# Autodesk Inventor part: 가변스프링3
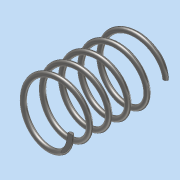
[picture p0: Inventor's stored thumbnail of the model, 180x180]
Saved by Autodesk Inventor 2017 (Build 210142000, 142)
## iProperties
Part Number: 가변스프링3
Material: 강철, 연강
Document SubType Name: Modeling
Designer: MRC
Density: 7.85 g/cm^3
Appearance: 반연마
Mass: 8.42502 g
Surface Area: 21.7259 cm^2
Volume: 1.07325 cm^3
Author: MRC
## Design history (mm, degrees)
sketch "스케치1"
  geometry: L1 (0, 0)-(11, 0); L2 (11, 0)-(11, 37.411); L3 (11, 37.411)-(0, 37.411); L4 (0, 37.411)-(0, 0); C1 r 1 at (11, 0)
  constraints: 8 end point, 2 parallel, 1 centre point, 1 coincident, 1 horizontal, 1 perpendicular
  dimensions: "d0" = 22 diameter of L2 L4; "d1" = 2 diameter of C1; "d2" = 37.4112 distance between parallel lines of L1 L3 (derived)
feature "코일1" sketch "스케치1" pitch "d3" = 10; turns "d5" = 5; dims "d4" = 37.4112 (= d2), "d6" = 0, angle "d7" = 90 deg, angle "d8" = 90 deg, "d9" = 0, "d10" = 0
sketch "스케치2"
  geometry: L1 (-25.076, 37.411)-(25.076, 37.411); L2 (25.076, 37.411)-(25.076, 0); L3 (25.076, 0)-(-25.076, 0); L4 (-25.076, 0)-(-25.076, 37.411); L5 (0, 37.411)-(0, 0) reference; 2 further points
  constraints: 8 end point, 2 midpoint, 2 parallel, 1 coincident, 1 horizontal, 1 perpendicular
  dimensions: "d11" = 50.15108 distance of L1.start L1.end
extrude "돌출1" sketch "스케치2" stored distance "d12" = 0; taper "d13" = 0 deg
node "솔리드1"
